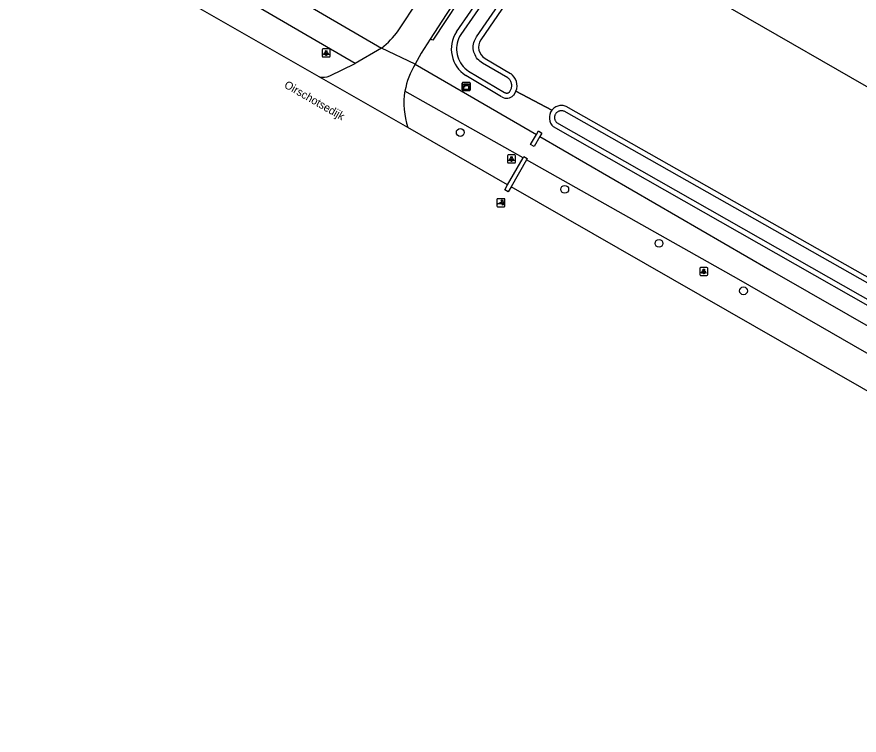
# Model space of a CAD drawing. Extents: x 157154 to 159278, y 385000 to 386650.
# Drawn here: x 158011.4 to 158116.6, y 385499.7 to 385589.4 of the extents above; entities that cross this region are included whole.
import ezdxf

# ---------------------------------------------------------------- set-up
doc = ezdxf.new("R2010")
doc.units = 0
for name, color, linetype in [('IMGEO_Boom', 7, 'Continuous'), ('IMGEO_Duiker', 7, 'Continuous'), ('IMGEO_Gemengd_bos', 7, 'Continuous'), ('IMGEO_Groenvoorziening', 7, 'Continuous'), ('IMGEO_Hek', 7, 'Continuous'), ('IMGEO_Kast', 7, 'Continuous'), ('IMGEO_Lichtpunt', 7, 'Continuous'), ('IMGEO_Muur', 7, 'Continuous'), ('IMGEO_Openbare_ruimte_label', 7, 'Continuous'), ('IMGEO_Poller', 7, 'Continuous'), ('IMGEO_Rijbaan_lokaal_gesloten', 7, 'Continuous'), ('IMGEO_Rijbaan_lokaal_open', 7, 'Continuous'), ('IMGEO_Voetpad_halfverhard', 7, 'Continuous'), ('IMGEO_Voetpad_open', 7, 'Continuous'), ('IMGEO_Waterloop', 7, 'Continuous')]:
    doc.layers.add(name, color=color, linetype=linetype)

msp = doc.modelspace()

# ---------------------------------------------------------------- linework, layer by layer
at = {"layer": 'IMGEO_Boom'}
for centre in [(158066.76, 385574.96), (158079.81, 385567.86), (158091.59, 385561.11), (158102.14, 385555.18)]:
    msp.add_circle(centre, 0.489, dxfattribs=at)
at = {"layer": 'IMGEO_Duiker'}
msp.add_lwpolyline([(158073.71, 385580.12), (158078.19, 385577.73)], dxfattribs=at)
at = {"layer": 'IMGEO_Gemengd_bos'}
for points in [[(158084.03, 385605.99), (158082.3, 385600.97), (158193.33, 385537.17), (158257.33, 385500.02), (158340.99, 385452.75), (158361.67, 385440.85)], [(158077.51, 385598.41), (158072.5, 385591.14), (158069.33, 385586.54)], [(158069.86, 385584.18), (158073.05, 385582.32)], [(158078.19, 385577.73), (158073.71, 385580.12)], [(158500, 385337.56), (158399.37, 385395.35), (158398.01, 385396.13), (158338.67, 385430.45), (158217.1, 385500), (158197.07, 385511.61), (158180.29, 385521.19), (158127.7, 385551.21), (158080, 385578.2), (158079.87, 385578.25), (158079.74, 385578.29), (158079.61, 385578.31), (158079.48, 385578.32), (158079.34, 385578.33), (158079.21, 385578.32), (158079.07, 385578.29), (158078.94, 385578.26), (158078.82, 385578.21), (158078.69, 385578.16), (158078.58, 385578.09), (158078.46, 385578.01), (158078.36, 385577.92), (158078.27, 385577.83), (158078.19, 385577.73)]]:
    msp.add_lwpolyline(points, dxfattribs=at)
for centre, radius, start, end in [((158070.67, 385585.6), 1.63, 145.0085, 240.2447), ((158071.99, 385580.8), 1.86, 338.4418, 54.8611)]:
    msp.add_arc(centre, radius, start, end, dxfattribs=at)
at = {"layer": 'IMGEO_Groenvoorziening'}
for points in [[(158066.27, 385587.53), (158069.87, 385592.72)], [(158071.93, 385579.39), (158067.45, 385582.06)], [(158073.71, 385580.12), (158073.41, 385579.59)], [(158519.78, 385323.32), (158514.58, 385326.04), (158500, 385334.39), (158452, 385361.87), (158421.45, 385379.13), (158397.77, 385392.7), (158303.54, 385446.74), (158210.59, 385500), (158178.61, 385518.44), (158148.23, 385535.97), (158078.39, 385575.67)]]:
    msp.add_lwpolyline(points, dxfattribs=at)
for centre, radius, start, end in [((158069.61, 385585.39), 3.97, 147.2928, 236.9181), ((158072.55, 385580.39), 1.17, 238.1843, 317.0761), ((158079.39, 385576.81), 1.51, 142.7144, 228.7785)]:
    msp.add_arc(centre, radius, start, end, dxfattribs=at)
at = {"layer": 'IMGEO_Hek'}
msp.add_lwpolyline([(158084.03, 385605.99), (158082.3, 385600.97), (158193.33, 385537.17), (158257.33, 385500.02)], dxfattribs=at)
at = {"layer": 'IMGEO_Kast'}
for p, q in [((158067.08, 385581.2), (158067.92, 385581.2)), ((158067.92, 385581.2), (158067.08, 385581.2)), ((158067, 385580.27), (158067, 385581.11)), ((158067, 385581.11), (158067, 385580.27)), ((158067.93, 385580.2), (158067.09, 385580.2)), ((158067.09, 385580.2), (158067.93, 385580.2)), ((158068, 385581.12), (158068, 385580.28)), ((158068, 385580.28), (158068, 385581.12))]:
    msp.add_line(p, q, dxfattribs=at)
for points in [[(158067.2, 385580.99), (158067.8, 385580.99), (158067.8, 385580.9), (158067.2, 385580.9), (158067.2, 385580.99)], [(158067.2, 385580.81), (158067.8, 385580.81), (158067.8, 385580.33), (158067.2, 385580.33), (158067.2, 385580.81)]]:
    msp.add_lwpolyline(points, dxfattribs=at)
msp.add_circle((158067.28, 385580.66), 0.0377, dxfattribs=at)
for centre, start, end in [((158067.08, 385581.12), 92.4484, 184.2845), ((158067.08, 385581.12), 92.4484, 184.2845), ((158067.92, 385581.12), 2.4484, 94.2845), ((158067.92, 385581.12), 2.4484, 94.2845), ((158067.08, 385580.28), 182.4484, 274.2845), ((158067.08, 385580.28), 182.4484, 274.2845), ((158067.92, 385580.28), 272.4484, 4.2845), ((158067.92, 385580.28), 272.4484, 4.2845)]:
    msp.add_arc(centre, 0.0779, start, end, dxfattribs=at)
at = {"layer": 'IMGEO_Lichtpunt'}
for p, q in [((158050.41, 385585.39), (158049.6, 385585.39)), ((158050.41, 385585.39), (158049.6, 385585.39)), ((158049.51, 385585.29), (158049.51, 385584.48)), ((158049.51, 385585.29), (158049.51, 385584.48)), ((158049.6, 385584.39), (158050.41, 385584.39)), ((158049.6, 385584.39), (158050.41, 385584.39)), ((158050.5, 385584.48), (158050.5, 385585.29)), ((158050.5, 385584.48), (158050.5, 385585.29)), ((158072.66, 385572.06), (158072.66, 385571.25)), ((158072.66, 385572.06), (158072.66, 385571.25)), ((158073.56, 385572.15), (158072.75, 385572.15)), ((158073.56, 385572.15), (158072.75, 385572.15)), ((158073.66, 385571.25), (158073.66, 385572.06)), ((158073.66, 385571.25), (158073.66, 385572.06)), ((158072.75, 385571.15), (158073.56, 385571.15)), ((158072.75, 385571.15), (158073.56, 385571.15)), ((158097.58, 385558.11), (158096.78, 385558.11)), ((158097.58, 385558.11), (158096.78, 385558.11)), ((158096.68, 385558.01), (158096.68, 385557.21)), ((158096.68, 385558.01), (158096.68, 385557.21)), ((158096.78, 385557.11), (158097.58, 385557.11)), ((158096.78, 385557.11), (158097.58, 385557.11)), ((158097.68, 385557.21), (158097.68, 385558.01)), ((158097.68, 385557.21), (158097.68, 385558.01))]:
    msp.add_line(p, q, dxfattribs=at)
for points in [[(158049.88, 385584.95), (158049.92, 385584.93), (158049.73, 385584.66), (158049.69, 385584.69), (158049.88, 385584.95)], [(158049.98, 385584.91), (158050.03, 385584.91), (158050.03, 385584.58), (158049.98, 385584.58), (158049.98, 385584.91)], [(158050.09, 385584.93), (158050.13, 385584.95), (158050.32, 385584.69), (158050.28, 385584.66), (158050.09, 385584.93)], [(158073.03, 385571.72), (158073.07, 385571.69), (158072.88, 385571.43), (158072.85, 385571.46), (158073.03, 385571.72)], [(158073.24, 385571.69), (158073.28, 385571.72), (158073.47, 385571.46), (158073.43, 385571.43), (158073.24, 385571.69)], [(158073.13, 385571.67), (158073.18, 385571.67), (158073.18, 385571.35), (158073.13, 385571.35), (158073.13, 385571.67)], [(158097.06, 385557.68), (158097.1, 385557.65), (158096.91, 385557.39), (158096.87, 385557.41), (158097.06, 385557.68)], [(158097.16, 385557.63), (158097.21, 385557.63), (158097.21, 385557.31), (158097.16, 385557.31), (158097.16, 385557.63)], [(158097.27, 385557.65), (158097.31, 385557.68), (158097.49, 385557.41), (158097.46, 385557.39), (158097.27, 385557.65)]]:
    msp.add_lwpolyline(points, dxfattribs=at)
for centre in [(158050.01, 385585.09), (158073.16, 385571.85), (158097.18, 385557.81)]:
    msp.add_circle(centre, 0.0994, dxfattribs=at)
for centre, start, end in [((158049.6, 385585.29), 90, 180), ((158049.6, 385585.29), 90, 180), ((158050.41, 385585.29), 0, 90), ((158050.41, 385585.29), 0, 90), ((158049.6, 385584.48), 180, 270), ((158049.6, 385584.48), 180, 270), ((158050.41, 385584.48), 270, 0), ((158050.41, 385584.48), 270, 360), ((158072.75, 385572.06), 90, 180), ((158072.75, 385572.06), 90, 180), ((158073.56, 385572.06), 0, 90), ((158073.56, 385572.06), 0, 90), ((158072.75, 385571.25), 180, 270), ((158072.75, 385571.25), 180, 270), ((158073.56, 385571.25), 270, 0), ((158073.56, 385571.25), 270, 360), ((158096.78, 385558.01), 90, 180), ((158096.78, 385558.01), 90, 180), ((158097.58, 385558.01), 0, 90), ((158097.58, 385558.01), 0, 90), ((158096.78, 385557.21), 180, 270), ((158096.78, 385557.21), 180, 270), ((158097.58, 385557.21), 270, 0), ((158097.58, 385557.21), 270, 360)]:
    msp.add_arc(centre, 0.0946, start, end, dxfattribs=at)
at = {"layer": 'IMGEO_Muur'}
for points in [[(158076.27, 385574.72), (158076.52, 385575.14), (158076.95, 385574.88), (158076.71, 385574.47)], [(158076.71, 385574.47), (158075.99, 385573.21), (158075.55, 385573.46), (158076.27, 385574.72)], [(158072.68, 385568.43), (158074.61, 385571.81)], [(158074.61, 385571.81), (158074.69, 385571.95), (158075.12, 385571.7), (158075.05, 385571.56)], [(158075.05, 385571.56), (158073.11, 385568.18)], [(158073.11, 385568.18), (158072.74, 385567.53), (158072.31, 385567.78), (158072.68, 385568.43)]]:
    msp.add_lwpolyline(points, dxfattribs=at)
at = {"layer": 'IMGEO_Poller'}
for p, q in [((158071.33, 385566.59), (158071.33, 385565.78)), ((158071.33, 385566.59), (158071.33, 385565.78)), ((158072.24, 385566.68), (158071.43, 385566.68)), ((158072.24, 385566.68), (158071.43, 385566.68)), ((158072.33, 385565.78), (158072.33, 385566.59)), ((158072.33, 385565.78), (158072.33, 385566.59)), ((158071.43, 385565.69), (158072.24, 385565.69)), ((158071.43, 385565.69), (158072.24, 385565.69))]:
    msp.add_line(p, q, dxfattribs=at)
for points in [[(158072.01, 385566.41), (158072, 385566.34), (158071.88, 385566.54)], [(158071.88, 385566.54), (158072.11, 385566.48), (158072.04, 385566.45)], [(158071.97, 385566.04), (158071.46, 385566.04), (158071.89, 385566.31)], [(158072.03, 385565.87), (158072.09, 385566.1), (158072.13, 385566.03)], [(158072.16, 385566), (158072.23, 385565.99), (158072.03, 385565.87)]]:
    msp.add_lwpolyline(points, dxfattribs=at)
for centre, radius, start, end in [((158071.43, 385566.59), 0.0946, 90, 180), ((158071.43, 385566.59), 0.0946, 90, 180), ((158071.65, 385566.1), 0.516, 349.3569, 42.2912), ((158072.24, 385566.59), 0.0946, 0, 90), ((158072.24, 385566.59), 0.0946, 0, 90), ((158071.43, 385565.78), 0.0946, 180, 270), ((158071.43, 385565.78), 0.0946, 180, 270), ((158071.64, 385566.09), 0.332, 351.3247, 42.4854), ((158071.65, 385566.1), 0.476, 351.7527, 41.1691), ((158072.24, 385565.78), 0.0946, 270, 0), ((158072.24, 385565.78), 0.0946, 270, 0)]:
    msp.add_arc(centre, radius, start, end, dxfattribs=at)
at = {"layer": 'IMGEO_Rijbaan_lokaal_gesloten'}
for points in [[(158049.13, 385581.9), (158016.2, 385600.76), (158013.74, 385602.42)], [(158067.77, 385593.97), (158065, 385589.69), (158063.02, 385586.6)], [(158059.02, 385587.64), (158061.55, 385591.51)], [(158063.02, 385586.6), (158061.89, 385584.85), (158061.14, 385583.49)], [(158056.93, 385585.48), (158053.65, 385583.55)], [(158061.14, 385583.49), (158056.93, 385585.48)], [(158050.47, 385582.02), (158053.65, 385583.55)], [(158060.23, 385575.56), (158049.13, 385581.9)], [(158072.68, 385568.43), (158060.23, 385575.56)], [(158513.29, 385316.25), (158356.14, 385406.04), (158073.11, 385568.18)]]:
    msp.add_lwpolyline(points, dxfattribs=at)
for centre, radius, start, end in [((158048.01, 385596.14), 13.91, 309.9338, 322.3319), ((158068.91, 385578.58), 9.19, 147.7046, 170.2889), ((158049.63, 385583.99), 2.15, 256.5906, 293.0499), ((158068.95, 385578.58), 9.23, 170.3019, 199.0761)]:
    msp.add_arc(centre, radius, start, end, dxfattribs=at)
at = {"layer": 'IMGEO_Rijbaan_lokaal_open'}
msp.add_lwpolyline([(158068.12, 385593.76), (158063.35, 385586.49), (158063.02, 385586.6)], dxfattribs=at)
at = {"layer": 'IMGEO_Voetpad_halfverhard'}
for points in [[(158012.6, 385611.42), (158037.1, 385597.03), (158056.93, 385585.48)], [(158053.65, 385583.55), (158034.95, 385594.47), (158011.37, 385607.44)]]:
    msp.add_lwpolyline(points, dxfattribs=at)
at = {"layer": 'IMGEO_Voetpad_open'}
for points in [[(158061.14, 385583.49), (158076.27, 385574.72)], [(158074.61, 385571.81), (158059.85, 385580.13)], [(158076.71, 385574.47), (158105.42, 385557.82), (158183.67, 385513.05), (158236.14, 385482.72), (158260.68, 385468.75), (158287.4, 385454.04), (158354.57, 385415.19)], [(158352.99, 385412.5), (158285.26, 385451.13), (158176.49, 385513.48), (158101.54, 385556.62), (158075.05, 385571.56)]]:
    msp.add_lwpolyline(points, dxfattribs=at)
at = {"layer": 'IMGEO_Waterloop'}
for points in [[(158070.43, 385592.38), (158066.82, 385587.17), (158066.67, 385586.92), (158066.55, 385586.66), (158066.45, 385586.39), (158066.38, 385586.11), (158066.33, 385585.83), (158066.3, 385585.55), (158066.3, 385585.26), (158066.32, 385584.98), (158066.37, 385584.69), (158066.44, 385584.41), (158066.54, 385584.15), (158066.66, 385583.88), (158066.8, 385583.64), (158066.96, 385583.4), (158067.14, 385583.18), (158067.34, 385582.97), (158067.56, 385582.79), (158067.79, 385582.62), (158072.27, 385579.95), (158072.31, 385579.93), (158072.35, 385579.91), (158072.39, 385579.9), (158072.44, 385579.89), (158072.48, 385579.88), (158072.52, 385579.87), (158072.57, 385579.87), (158072.61, 385579.88), (158072.65, 385579.88), (158072.7, 385579.89), (158072.74, 385579.91), (158072.78, 385579.92), (158072.82, 385579.94), (158072.85, 385579.97), (158072.89, 385579.99), (158073.12, 385580.4), (158073.15, 385580.5), (158073.17, 385580.6), (158073.18, 385580.7), (158073.19, 385580.8), (158073.18, 385580.9), (158073.17, 385581.01), (158073.15, 385581.11), (158073.12, 385581.2), (158073.08, 385581.3), (158073.04, 385581.39), (158072.98, 385581.48), (158072.92, 385581.56), (158072.85, 385581.64), (158072.78, 385581.71), (158072.7, 385581.77), (158069.53, 385583.61), (158069.36, 385583.72), (158069.21, 385583.84), (158069.06, 385583.98), (158068.92, 385584.12), (158068.8, 385584.28), (158068.69, 385584.45), (158068.6, 385584.63), (158068.52, 385584.81), (158068.46, 385585), (158068.42, 385585.2), (158068.39, 385585.39), (158068.38, 385585.59), (158068.39, 385585.79), (158068.42, 385585.99), (158068.46, 385586.19), (158068.52, 385586.38), (158068.6, 385586.56), (158068.69, 385586.74), (158068.8, 385586.91), (158071.94, 385591.47)], [(158127.38, 385550.64), (158079.72, 385577.61), (158079.66, 385577.63), (158079.59, 385577.65), (158079.52, 385577.66), (158079.44, 385577.67), (158079.36, 385577.67), (158079.29, 385577.67), (158079.21, 385577.65), (158079.14, 385577.63), (158079.06, 385577.61), (158078.99, 385577.58), (158078.93, 385577.54), (158078.86, 385577.49), (158078.81, 385577.44), (158078.75, 385577.39), (158078.7, 385577.33), (158078.66, 385577.26), (158078.62, 385577.2), (158078.59, 385577.12), (158078.56, 385577.05), (158078.55, 385576.98), (158078.54, 385576.9), (158078.53, 385576.83), (158078.53, 385576.75), (158078.54, 385576.67), (158078.56, 385576.6), (158078.58, 385576.53), (158078.61, 385576.46), (158078.64, 385576.39), (158078.68, 385576.32), (158078.73, 385576.26), (158078.78, 385576.21), (158148.56, 385536.53)]]:
    msp.add_lwpolyline(points, dxfattribs=at)

# ---------------------------------------------------------------- texts
at = {"layer": 'IMGEO_Openbare_ruimte_label'}
msp.add_text('Oirschotsedijk', height=1, rotation=330.1272, dxfattribs=at).set_placement((158044.67, 385580.62))

doc.saveas('drawing.dxf')
